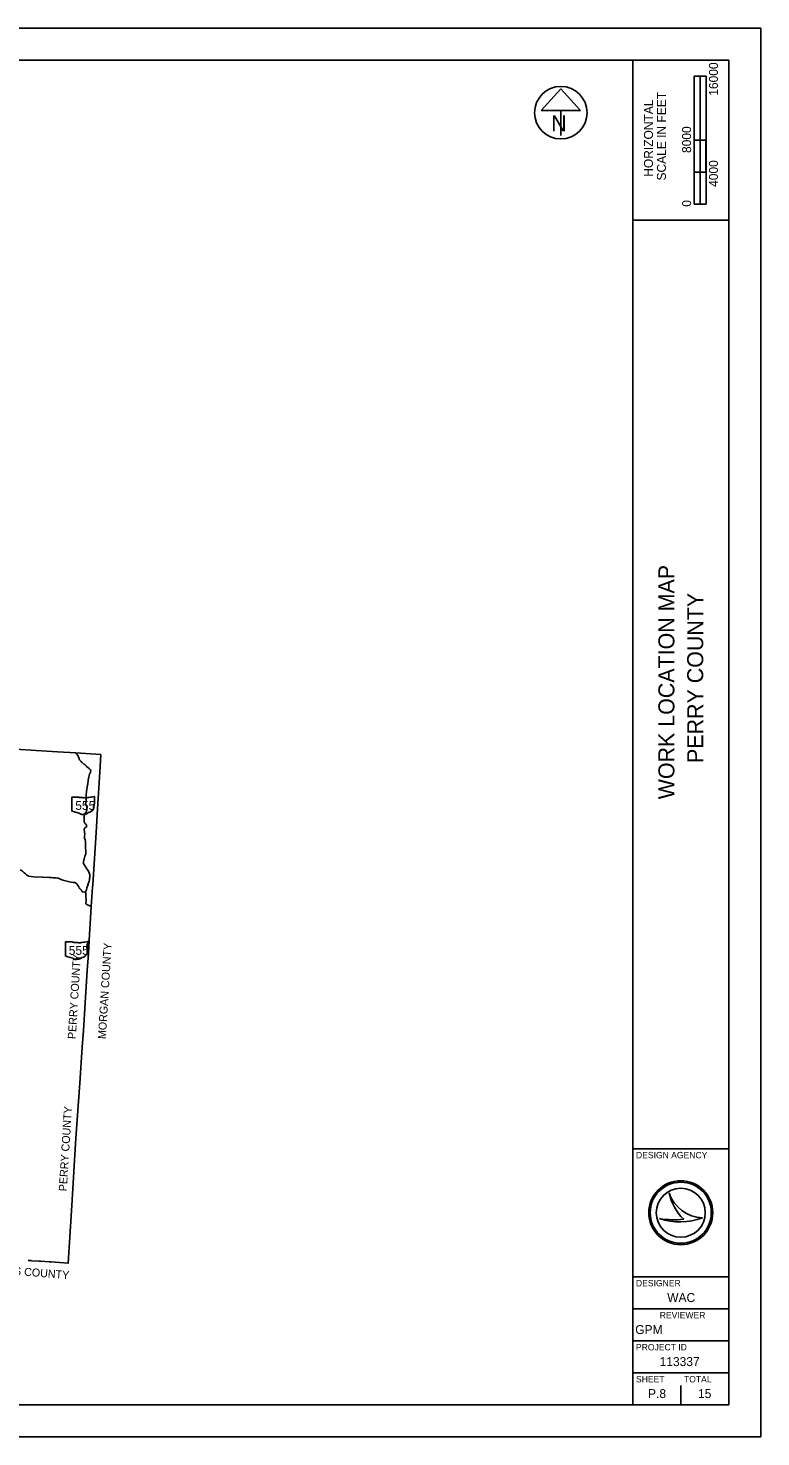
# Model space of a CAD drawing. Extents: x 1912787 to 2184787, y 543251 to 719251.
# Drawn here: x 2093246 to 2184787, y 543251 to 719251 of the extents above; entities that cross this region are included whole.
import ezdxf

# ---------------------------------------------------------------- set-up
doc = ezdxf.new("R2010")
doc.units = 0
for name, color, linetype in [('GM_X_County', 7, 'Continuous'), ('GM_X_County_Text', 7, 'Continuous'), ('GM_X_State_Location', 7, 'Continuous'), ('GM_X_State_Route', 7, 'Continuous'), ('GM_X_State_Shield', 7, 'Continuous'), ('SH_Border', 7, 'Continuous'), ('SH_Cut_Line', 7, 'Continuous'), ('SH_Data', 7, 'Continuous'), ('SH_Masking', 7, 'Continuous'), ('SH_Text', 7, 'Continuous')]:
    doc.layers.add(name, color=color, linetype=linetype)

msp = doc.modelspace()

# ---------------------------------------------------------------- linework, layer by layer
at = {"layer": 'GM_X_County'}
msp.add_lwpolyline([(2090938, 629224), (2096895, 628847), (2099187, 628710), (2102312, 628487), (2102193, 626283), (2101908, 621725), (2101721, 618763), (2101311, 612237), (2101290, 611908), (2101137, 609504), (2100881, 605294), (2100816, 604427), (2100776, 603648), (2100631, 601508), (2100343, 596816), (2100327, 596770), (2100147, 594037), (2099987, 591925), (2099681, 587430), (2099218, 580571), (2098707, 572170), (2098250, 564948), (2096075, 565106), (2095873, 565126), (2094827, 565192), (2094797, 565200), (2094779, 565204), (2094764, 565207), (2094750, 565209), (2094740, 565211), (2094727, 565212), (2094716, 565212), (2094701, 565213), (2094683, 565212), (2094668, 565211), (2094648, 565210), (2094631, 565207), (2094613, 565204), (2093651, 565260), (2093610, 565267), (2093571, 565272), (2093538, 565275), (2093505, 565278), (2093473, 565281), (2093444, 565283), (2093421, 565284), (2093383, 565286), (2093357, 565287), (2093335, 565287), (2093279, 565284), (2093242, 565282)], dxfattribs=at)
at = {"layer": 'GM_X_State_Route'}
for points in [[(2099600, 627994), (2099570, 628077), (2099522, 628214), (2099451, 628392), (2099374, 628518), (2099298, 628605), (2099188, 628707)], [(2101076, 626465), (2101081, 626479), (2101088, 626513), (2100994, 626609), (2100806, 626799), (2100700, 626898), (2100545, 626998), (2100502, 627052), (2100472, 627100), (2100453, 627131), (2100427, 627169), (2100408, 627187), (2100370, 627213), (2100312, 627242), (2100254, 627266), (2100196, 627297), (2100151, 627330), (2100111, 627364), (2099976, 627498), (2099922, 627559), (2099883, 627610), (2099831, 627677), (2099793, 627720), (2099748, 627765), (2099661, 627851), (2099626, 627921), (2099600, 627994)], [(2100572, 621814), (2100571, 621851), (2100568, 621979), (2100564, 622050), (2100492, 622189), (2100433, 622306), (2100418, 622362), (2100421, 622417), (2100438, 622470), (2100450, 622524), (2100481, 622839), (2100512, 623284), (2100512, 623462), (2100543, 623875), (2100669, 624702), (2100686, 624812), (2100760, 625292), (2100818, 625708), (2100851, 625884), (2100904, 626052), (2101021, 626309), (2101076, 626465)], [(2100227, 620259), (2100227, 620264), (2100229, 620349), (2100237, 620530), (2100238, 620563), (2100243, 620639), (2100243, 620701), (2100248, 620763), (2100256, 620821), (2100264, 620861), (2100289, 620950), (2100298, 620979), (2100310, 621008), (2100324, 621040), (2100336, 621063), (2100346, 621082), (2100374, 621129), (2100438, 621236), (2100484, 621313), (2100499, 621347), (2100508, 621372), (2100524, 621411), (2100538, 621450), (2100548, 621475), (2100552, 621492), (2100557, 621524), (2100560, 621544), (2100562, 621562), (2100566, 621601), (2100569, 621651), (2100569, 621699), (2100573, 621771), (2100572, 621814)], [(2100408, 611276), (2100464, 611414), (2100522, 611579), (2100591, 611844), (2100652, 612054), (2100742, 612343), (2100851, 612691), (2100894, 612858), (2100934, 613401), (2100932, 613525), (2100914, 613602), (2100870, 613699), (2100765, 613917), (2100585, 614226), (2100150, 614888), (2100131, 614961), (2100158, 615103), (2100330, 615799), (2100339, 615853), (2100350, 615895), (2100407, 616002), (2100438, 616062), (2100460, 616142), (2100427, 617136), (2100421, 617330), (2100428, 617496), (2100415, 617625), (2100354, 617832), (2100302, 618054), (2100274, 618180), (2100298, 618326), (2100309, 618521), (2100282, 618858), (2100241, 619116), (2100244, 619190), (2100271, 619254), (2100323, 619321), (2100558, 619494), (2100573, 619505), (2100586, 619514), (2100524, 619673), (2100407, 619847), (2100336, 619933), (2100281, 620014), (2100242, 620104), (2100237, 620123), (2100232, 620154), (2100228, 620186), (2100227, 620219), (2100227, 620259)], [(2092257, 614093), (2092407, 614019), (2092552, 613916), (2092757, 613724), (2092892, 613584), (2093069, 613433), (2093147, 613380), (2093234, 613338), (2093291, 613301), (2093344, 613282)], [(2093344, 613282), (2093921, 613233), (2095034, 613160)], [(2095034, 613160), (2095087, 613157), (2095851, 613117), (2096017, 613132), (2096109, 613128), (2096378, 613103), (2096525, 613096), (2096675, 613073), (2096929, 613058), (2097023, 613035), (2097154, 612983), (2097348, 612871), (2097595, 612783), (2098082, 612674), (2098421, 612602), (2098618, 612563), (2098871, 612516), (2099060, 612491), (2099171, 612457), (2099254, 612416), (2099326, 612338), (2099417, 612202), (2099470, 612148), (2099507, 612108), (2099565, 611968), (2099638, 611820), (2099691, 611762), (2099778, 611682), (2099849, 611607), (2099902, 611527), (2100011, 611349), (2100089, 611326), (2100275, 611300), (2100361, 611290), (2100408, 611276)], [(2100408, 611276), (2100432, 611248), (2100439, 611215), (2100444, 611101), (2100460, 610757), (2100484, 610316), (2100478, 610176), (2100465, 609961), (2100458, 609858), (2100465, 609825)], [(2100465, 609825), (2100485, 609797), (2100525, 609772), (2100578, 609761), (2100755, 609696), (2101138, 609501)], [(2100777, 603645), (2100702, 603918), (2100646, 604087), (2100602, 604252), (2100580, 604393), (2100579, 604512), (2100581, 604585), (2100597, 604681), (2100628, 604766), (2100667, 604862), (2100719, 604962), (2100882, 605291)]]:
    msp.add_lwpolyline(points, dxfattribs=at)
at = {"layer": 'GM_X_State_Shield'}
for p, q in [((2098713, 623153), (2098713, 621452)), ((2099561, 623182), (2098741, 623182)), ((2101515, 622334), (2101515, 623224)), ((2101515, 622334), (2101515, 622334)), ((2097900, 605048), (2097900, 603347)), ((2098748, 605077), (2097927, 605077)), ((2100701, 604230), (2100701, 605119)), ((2100701, 604230), (2100701, 604230))]:
    msp.add_line(p, q, dxfattribs=at)
for centre, major_axis, start_param, end_param in [((2098745, 623156), (32.5, 0), 1.7126934, 3.2834897), ((2099757, 623380), (315, 0), 4.042523, 4.731795), ((2099861, 622227), (1130, 0), 1.4047578, 1.6578581), ((2100118, 623165), (90.8, 0), 3.8360951, 5.1854146), ((2100251, 622969), (189, 0), 0.950623, 2.079405), ((2100495, 623238), (227, 0), 4.0815608, 5.1457227), ((2100896, 622662), (598, 0), 1.6990114, 2.1078141), ((2100517, 625501), (2971, 0), 4.8143942, 5.0423688), ((2101484, 623228), (31.2, 0), 6.1411519, 7.9890352), ((2098746, 621448), (32.7, 0), 3.00124, 4.5083009), ((2098751, 621622), (250, 0), 4.6659457, 4.8974612), ((2098802, 621353), (90.1, 0), 0.5192072, 1.6278991), ((2099939, 622882), (2146, 0), 4.1959971, 4.4889607), ((2100997, 620974), (407, 0), 1.6476453, 2.4884337), ((2100684, 621849), (743, 0), 5.1017525, 6.4400178), ((2101627, 621962), (211, 0), 2.3877238, 3.2625369), ((2101508, 622269), (48.3, 0), 1.8839779, 3.6710726), ((2101201, 622156), (290, 0), 5.9346948, 6.6959481), ((2101482, 622331), (33.4, 0), 5.05454, 6.4181714), ((2099300, 620687), (671, 0), 0.8235189, 1.3235874), ((2100026, 621345), (426, 0), 4.0264811, 4.9967352), ((2100272, 620757), (350, 0), 1.495662, 1.9409797), ((2100303, 621218), (227, 0), 4.6910439, 5.5073738), ((2100508, 621053), (63.9, 0), 1.1475842, 2.3151517), ((2100481, 621287), (240, 0), 4.9370686, 5.64225), ((2097932, 605052), (32.5, 0), 1.7126934, 3.2834897), ((2098943, 605275), (315, 0), 4.042523, 4.731795), ((2099047, 604122), (1130, 0), 1.4047578, 1.6578581), ((2099304, 605060), (90.8, 0), 3.8360951, 5.1854146), ((2099437, 604864), (189, 0), 0.950623, 2.079405), ((2099681, 605134), (227, 0), 4.0815608, 5.1457227), ((2100082, 604558), (598, 0), 1.6990114, 2.1078141), ((2099703, 607397), (2971, 0), 4.8143942, 5.0423688), ((2099870, 603744), (743, 0), 5.1017525, 6.4400178), ((2100813, 603857), (211, 0), 2.3877238, 3.2625369), ((2100694, 604164), (48.3, 0), 1.8839779, 3.6710726), ((2100387, 604052), (290, 0), 5.9346948, 6.6959481), ((2100670, 605123), (31.2, 0), 6.1411519, 7.9890352), ((2100668, 604226), (33.4, 0), 5.05454, 6.4181714), ((2097932, 603343), (32.7, 0), 3.00124, 4.5083009), ((2097937, 603517), (250, 0), 4.6659457, 4.8974612), ((2097988, 603249), (90.1, 0), 0.5192072, 1.6278991), ((2099126, 604777), (2146, 0), 4.1959971, 4.4889607), ((2098486, 602583), (671, 0), 0.8235189, 1.3235874), ((2099212, 603240), (426, 0), 4.0264811, 4.9967352), ((2099458, 602652), (350, 0), 1.495662, 1.9409797), ((2099489, 603113), (227, 0), 4.6910439, 5.5073738), ((2099695, 602948), (63.9, 0), 1.1475842, 2.3151517), ((2099667, 603182), (240, 0), 4.9370686, 5.64225), ((2100183, 602869), (407, 0), 1.6476453, 2.4884337)]:
    msp.add_ellipse(centre, major_axis=major_axis, ratio=0.8, start_param=start_param, end_param=end_param, dxfattribs=at)
at = {"layer": 'SH_Border'}
for p, q in [((2168787, 547251), (2168787, 715251)), ((2168787, 695251), (2180787, 695251)), ((2168787, 579251), (2180787, 579251)), ((2168787, 563251), (2180787, 563251)), ((2168787, 559251), (2180787, 559251)), ((2168787, 555251), (2180787, 555251)), ((2168787, 551251), (2180787, 551251))]:
    msp.add_line(p, q, dxfattribs=at)
msp.add_lwpolyline([(1924787, 715251), (2180787, 715251), (2180787, 547251), (1924787, 547251)], close=True, dxfattribs=at)
at = {"layer": 'SH_Cut_Line'}
msp.add_lwpolyline([(1912787, 543251), (2184787, 543251), (2184787, 719251), (1912787, 719251)], close=True, dxfattribs=at)
at = {"layer": 'SH_Data'}
for p, q in [((2176440, 697251), (2176440, 713251)), ((2177940, 713251), (2176440, 713251)), ((2176440, 705251), (2176440, 713251)), ((2176440, 713251), (2177187, 713251)), ((2177187, 713251), (2177193, 713251)), ((2177193, 713251), (2177193, 705251)), ((2177940, 713251), (2177940, 697251)), ((2177193, 705251), (2176440, 705251)), ((2177933, 705251), (2177187, 705251)), ((2177187, 705251), (2177187, 701251)), ((2177933, 701251), (2177933, 705251)), ((2177187, 701251), (2176440, 701251)), ((2176440, 701251), (2176440, 697251)), ((2177187, 697251), (2177187, 701251)), ((2177187, 701251), (2177933, 701251)), ((2177940, 697251), (2176440, 697251)), ((2176440, 697251), (2177187, 697251)), ((2173326, 573727), (2173326, 573727)), ((2172124, 570527), (2172124, 570527)), ((2174787, 571251), (2174787, 571251)), ((2177485, 570599), (2177485, 570599)), ((2174787, 547251), (2174787, 549651)), ((2171787, 548651), (2171787, 548651))]:
    msp.add_line(p, q, dxfattribs=at)
for radius in [4000, 3814, 3814, 3058]:
    msp.add_circle((2174787, 571251), radius, dxfattribs=at)
for centre, radius, start, end in [((2177714, 575232), 4639, 198.92567, 198.93195), ((2179560, 575011), 6365, 191.63793, 191.64215), ((2177714, 575232), 4639, 198.93195, 267.16574), ((2179560, 575011), 6365, 191.64215, 226.09467), ((2173971, 580486), 10128, 259.49639, 259.49952), ((2174702, 578211), 8105, 251.45274, 251.45764), ((2174702, 578211), 8105, 251.45764, 290.08324), ((2173971, 580486), 10128, 259.49952, 276.66723)]:
    msp.add_arc(centre, radius, start, end, dxfattribs=at)
at = {"layer": 'SH_Masking'}
msp.add_circle((2159798, 708690), 3280, dxfattribs=at)
at = {"layer": 'SH_Text'}
for p, q in [((2159798, 711680), (2157337, 708950)), ((2162259, 708950), (2159798, 711680)), ((2157337, 708950), (2162259, 708950)), ((2159798, 708950), (2159798, 705856))]:
    msp.add_line(p, q, dxfattribs=at)
msp.add_circle((2159798, 708690), 3280, dxfattribs=at)

# ---------------------------------------------------------------- texts
at = {"layer": 'GM_X_County_Text'}
for s, rotation, p in [('MORGAN COUNTY', 86.46062, (2102945, 592922)), ('PERRY COUNTY', 86.46062, (2099187, 592922)), ('PERRY COUNTY', 86.41019, (2098062, 573907)), ('ATHENS COUNTY', 355.51231, (2086932, 563846))]:
    msp.add_text(s, height=1000, rotation=rotation, dxfattribs=at).set_placement(p)
at = {"layer": 'GM_X_State_Location'}
for p in [(2100056, 622307), (2100777, 607246), (2100228, 604293)]:
    msp.add_text('555', height=1, rotation=0.00001, dxfattribs=at).set_placement(p)
for s, p in [('s', (2100409, 622380)), ('r', (2100409, 622380)), ('s', (2101130, 607319)), ('r', (2101130, 607319)), ('s', (2100581, 604366)), ('r', (2100581, 604366))]:
    msp.add_text(s, height=1, dxfattribs=at).set_placement(p)
at = {"layer": 'GM_X_State_Shield'}
for p in [(2099131, 621572), (2098317, 603467)]:
    msp.add_text('555', height=1120.7, dxfattribs=at).set_placement(p)
at = {"layer": 'SH_Data'}
for s, height, p in [('16000', 1120, (2179429, 710810)), ('SCALE IN FEET', 1120, (2172927, 700216)), ('HORIZONTAL', 1120, (2171307, 700685)), ('8000', 1120, (2176071, 703656)), ('4000', 1120, (2179429, 699419)), ('0', 1120, (2176071, 696941)), ('WORK LOCATION MAP', 2000, (2173987, 622909)), ('PERRY COUNTY', 2000, (2177587, 627447))]:
    msp.add_text(s, height=height, rotation=90, dxfattribs=at).set_placement(p)
for s, height, p in [('DESIGN AGENCY', 800, (2169187, 578051)), ('DESIGNER', 800, (2169187, 562051)), ('WAC', 1120, (2173091, 560091)), ('REVIEWER', 800, (2172161, 558051)), ('GPM', 1120, (2169094, 556091)), ('PROJECT ID', 800, (2169187, 554051)), ('113337', 1120, (2172146, 552091)), ('SHEET', 800, (2169187, 550051)), ('P.8', 1120, (2170697, 548091)), ('TOTAL', 800, (2175187, 550051)), ('15', 1120, (2176944, 548091))]:
    msp.add_text(s, height=height, dxfattribs=at).set_placement(p)
at = {"layer": 'SH_Text'}
msp.add_text('N', height=2000, dxfattribs=at).set_placement((2158588, 706359))

doc.saveas('drawing.dxf')
